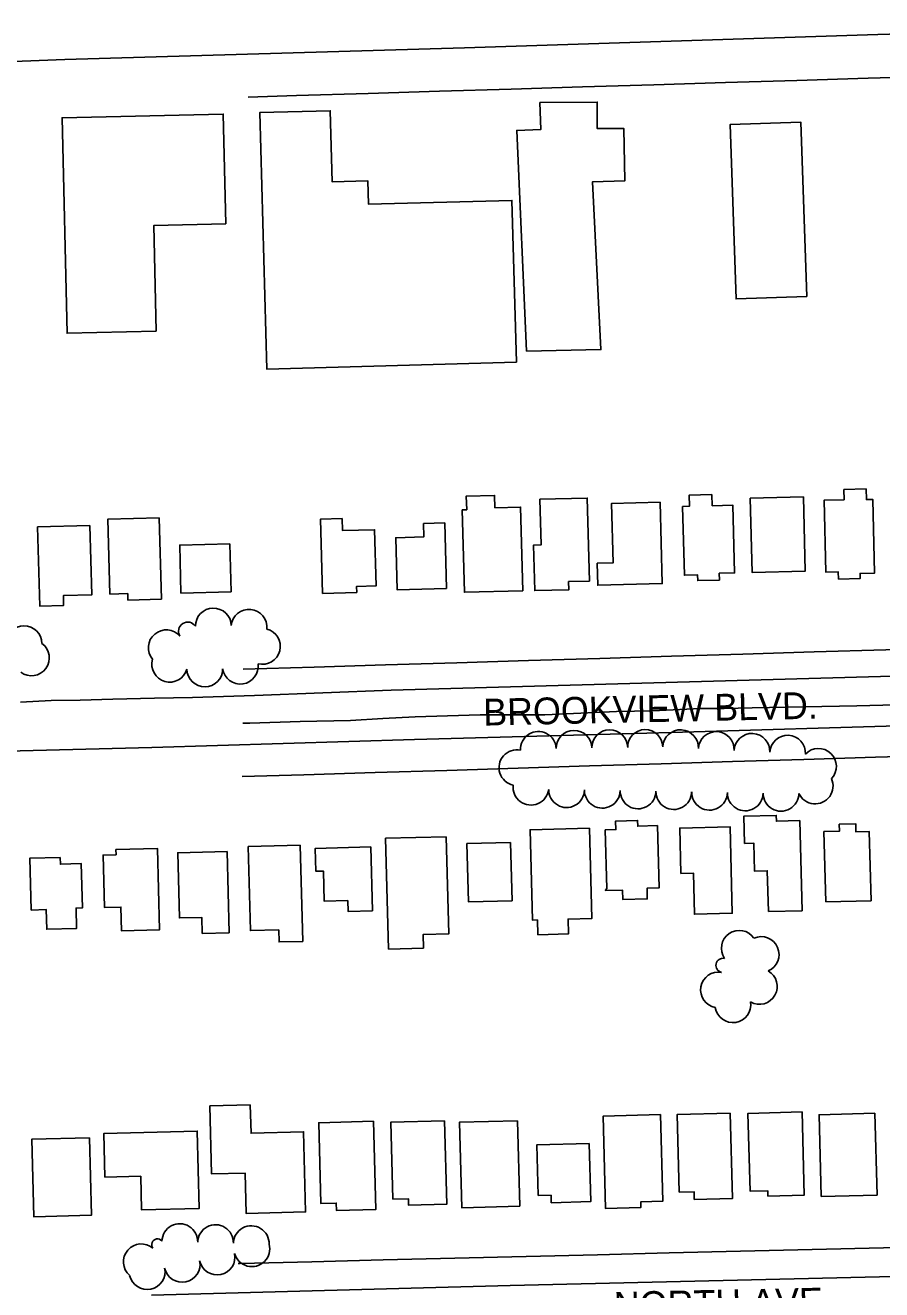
# Model space of a CAD drawing. Extents: x -25029 to 2274964, y -81170 to 687028.
# Drawn here: x -18487 to -18008, y -65240 to -64533 of the extents above; entities that cross this region are included whole.
import ezdxf

# ---------------------------------------------------------------- set-up
doc = ezdxf.new("R2010")
doc.units = 0
for name, color, linetype in [('81911BEA - RW_X_Fee_RW', 7, 'Continuous'), ('BLDG', 7, 'Continuous'), ('GE_X_CL_2000', 7, 'Continuous'), ('ROAD', 7, 'Continuous'), ('ROAD-NAME', 7, 'Continuous'), ('TREES', 7, 'Continuous')]:
    doc.layers.add(name, color=color, linetype=linetype)

msp = doc.modelspace()

# ---------------------------------------------------------------- linework, layer by layer
at = {"layer": '81911BEA - RW_X_Fee_RW'}
for points in [[(-17756.21, -64554.32), (-17775.8, -64554.92), (-17815.79, -64556.13), (-17855.77, -64557.35), (-17895.75, -64558.56), (-17935.73, -64559.78), (-17975.72, -64561), (-18015.7, -64562.21), (-18055.68, -64563.43)], [(-18055.68, -64563.43), (-18095.66, -64564.64), (-18135.65, -64565.86), (-18175.63, -64567.07), (-18215.61, -64568.29), (-18255.59, -64569.5), (-18295.58, -64570.72), (-18335.56, -64571.93), (-18362.69, -64572.76)], [(-17754.05, -64874.38), (-17846.04, -64877.18), (-17886.02, -64878.4), (-17926, -64879.61), (-17965.98, -64880.83), (-18005.96, -64882.04), (-18045.95, -64883.26)], [(-18045.95, -64883.26), (-18085.93, -64884.47), (-18125.91, -64885.69), (-18165.89, -64886.9), (-18205.88, -64888.12), (-18245.86, -64889.34), (-18285.84, -64890.55), (-18325.83, -64891.77), (-18365.44, -64892.97)], [(-17752.23, -64934.36), (-17851.79, -64937.38), (-17891.77, -64938.6), (-17931.76, -64939.82), (-17971.74, -64941.03), (-18011.72, -64942.25), (-18051.7, -64943.46)], [(-18051.7, -64943.46), (-18091.69, -64944.68), (-18131.67, -64945.89), (-18171.65, -64947.11), (-18211.63, -64948.32), (-18251.62, -64949.54), (-18291.6, -64950.75), (-18331.58, -64951.97), (-18365.96, -64953.01)], [(-17728.73, -65209.91), (-17847.23, -65212.8), (-17887.22, -65213.77), (-17927.21, -65214.75), (-17947.2, -65215.24), (-17967.2, -65215.72), (-18007.19, -65216.7), (-18047.18, -65217.67)], [(-18047.18, -65217.67), (-18087.16, -65218.65), (-18127.15, -65219.62), (-18167.14, -65220.6), (-18207.13, -65221.58), (-18247.12, -65222.55), (-18287.11, -65223.53), (-18327.1, -65224.5), (-18367.09, -65225.48), (-18368.31, -65225.5)]]:
    msp.add_lwpolyline(points, dxfattribs=at)
at = {"layer": 'BLDG'}
for points in [[(-18212.62, -64721.2), (-18215.12, -64630.57), (-18295.29, -64632.78), (-18295.65, -64619.71), (-18315.62, -64620.26), (-18316.72, -64580.41), (-18356.17, -64581.5), (-18352.21, -64725.05)], [(-18207.02, -64715.01), (-18212.41, -64591.45), (-18198.99, -64590.97), (-18199.41, -64575.88), (-18167.33, -64575.54), (-18167.47, -64590.28), (-18152.56, -64590.35), (-18152.01, -64619.65), (-18170.01, -64620.2), (-18165.28, -64714.06)], [(-18414.09, -64703.77), (-18415.47, -64644.64), (-18375.23, -64643.7), (-18376.66, -64582.3), (-18466.78, -64584.39), (-18463.98, -64704.93)], [(-18050.1, -64684.33), (-18053.48, -64586.79), (-18093.05, -64588.16), (-18089.67, -64685.7)], [(-18029.21, -64798.08), (-18029.36, -64792.39), (-18016.92, -64792.07), (-18016.77, -64798.03), (-18013.24, -64797.93), (-18012.17, -64839.11), (-18020.33, -64839.33), (-18020.26, -64842.2), (-18032.36, -64842.52), (-18032.47, -64838.49), (-18039.38, -64838.67), (-18040.43, -64798.37)], [(-18209, -64849.04), (-18210.22, -64802.24), (-18224.66, -64802.62), (-18224.84, -64795.66), (-18240.62, -64796.07), (-18240.42, -64803.73), (-18242.87, -64803.8), (-18241.67, -64849.9)], [(-18199.43, -64797.86), (-18198.76, -64823.37), (-18202.97, -64823.48), (-18202.3, -64848.96), (-18183.26, -64848.46), (-18183.38, -64843.93), (-18171.72, -64843.62), (-18172.93, -64797.17)], [(-18132.23, -64799.46), (-18131.04, -64845), (-18167.08, -64845.94), (-18167.4, -64833.69), (-18158.5, -64833.45), (-18159.37, -64800.17)], [(-18103.13, -64801.49), (-18103.29, -64795.26), (-18115.96, -64795.59), (-18115.8, -64801.8), (-18119.6, -64801.9), (-18118.6, -64840.34), (-18111.23, -64840.14), (-18111.14, -64843.38), (-18099, -64843.07), (-18099.1, -64839.28), (-18090.5, -64839.06), (-18091.49, -64801.19)], [(-18081.84, -64797.29), (-18080.76, -64838.8), (-18050.95, -64838.02), (-18052.04, -64796.51)], [(-18451.2, -64812.54), (-18450.19, -64851.34), (-18466.08, -64851.76), (-18465.94, -64857.25), (-18479.35, -64857.6), (-18480.51, -64813.31)], [(-18412.42, -64808.17), (-18411.23, -64853.73), (-18429.96, -64854.22), (-18430.05, -64850.63), (-18440.03, -64850.89), (-18441.13, -64808.92)], [(-18310.03, -64808.63), (-18309.85, -64815.37), (-18291.97, -64814.9), (-18291.15, -64846.35), (-18301.99, -64846.63), (-18301.9, -64849.99), (-18321.08, -64850.49), (-18322.17, -64808.95)], [(-18264.66, -64811.44), (-18264.47, -64818.94), (-18280.08, -64819.35), (-18279.32, -64848.47), (-18251.73, -64847.74), (-18252.69, -64811.12)], [(-18372.97, -64822.74), (-18372.26, -64849.61), (-18400.29, -64850.35), (-18401, -64823.48)], [(-18071.61, -65028.59), (-18072.21, -65005.74), (-18079.43, -65005.93), (-18079.84, -64990.26), (-18084.97, -64990.4), (-18085.37, -64975.23), (-18067.22, -64974.76), (-18067.13, -64978.01), (-18054.09, -64977.67), (-18052.77, -65028.09)], [(-18171.68, -64981.95), (-18170.36, -65032.42), (-18183.71, -65032.77), (-18183.49, -65041.12), (-18200.58, -65041.56), (-18200.8, -65033.26), (-18203.61, -65033.33), (-18204.94, -64982.82)], [(-18162.96, -65016.85), (-18153.16, -65016.6), (-18153.02, -65021.87), (-18139.35, -65021.51), (-18139.51, -65015.48), (-18132.76, -65015.3), (-18133.67, -64980.5), (-18144.69, -64980.79), (-18144.77, -64977.6), (-18157.07, -64977.93), (-18156.95, -64982.74), (-18162.89, -64982.9), (-18162.03, -65015.71)], [(-18120.54, -65007.25), (-18113.59, -65007.07), (-18112.98, -65030.04), (-18091.79, -65029.49), (-18093.06, -64981.1), (-18121.21, -64981.83)], [(-18039.53, -65023.22), (-18040.56, -64983.85), (-18031.88, -64983.62), (-18031.98, -64979.71), (-18022.76, -64979.47), (-18022.64, -64984.04), (-18015.15, -64983.84), (-18014.14, -65022.56)], [(-18345.55, -65038.77), (-18345.37, -65045.59), (-18332.19, -65045.24), (-18333.6, -64991.43), (-18362.64, -64992.19), (-18361.41, -65039.18)], [(-18251.9, -64986.71), (-18250.48, -65041.05), (-18264.83, -65041.43), (-18264.63, -65049.04), (-18284.14, -65049.55), (-18285.76, -64987.59)], [(-18215.91, -64989.93), (-18215.05, -65022.54), (-18239.39, -65023.18), (-18240.25, -64990.57)], [(-18467.88, -64998.23), (-18467.78, -65002.05), (-18456.08, -65001.74), (-18455.43, -65026.52), (-18458.96, -65026.62), (-18458.66, -65038.04), (-18475.35, -65038.48), (-18475.64, -65027.51), (-18484.05, -65027.74), (-18484.81, -64998.67)], [(-18436.7, -64993.88), (-18436.63, -64996.79), (-18443.9, -64996.98), (-18443.13, -65026.29), (-18433.86, -65026.05), (-18433.51, -65039.39), (-18412.31, -65038.83), (-18413.5, -64993.27)], [(-18374.52, -64994.98), (-18373.33, -65040.44), (-18388.42, -65040.83), (-18388.65, -65031.82), (-18401.13, -65032.14), (-18402.08, -64995.7)], [(-18293.19, -65028.12), (-18306.79, -65028.47), (-18306.95, -65022.42), (-18320.12, -65022.76), (-18320.56, -65005.94), (-18324.79, -65006.05), (-18325.12, -64993.22), (-18294.12, -64992.41)], [(-18361.49, -65136.75), (-18361.07, -65152.59), (-18331.71, -65151.82), (-18330.54, -65196.64), (-18363.87, -65197.52), (-18364.46, -65174.9), (-18383.12, -65175.39), (-18384.11, -65137.34)], [(-18292.49, -65145.91), (-18291.2, -65195.23), (-18313.3, -65195.81), (-18313.41, -65191.74), (-18321.98, -65191.97), (-18323.17, -65146.71)], [(-18252.81, -65145.62), (-18251.59, -65192.4), (-18272.91, -65192.96), (-18273.01, -65189.25), (-18281.67, -65189.48), (-18282.8, -65146.4)], [(-18211.95, -65145.66), (-18210.7, -65193.43), (-18243.2, -65194.28), (-18244.45, -65146.51)], [(-18131.98, -65142.19), (-18130.71, -65190.72), (-18143.06, -65191.04), (-18142.98, -65194.26), (-18162.68, -65194.77), (-18164.03, -65143.03)], [(-18092.91, -65141.31), (-18091.66, -65189.07), (-18113.05, -65189.63), (-18113.16, -65185.34), (-18121.45, -65185.56), (-18122.59, -65142.09)], [(-18052.74, -65140.72), (-18051.52, -65187.23), (-18071.85, -65187.77), (-18071.92, -65184.77), (-18081.88, -65185.03), (-18083.02, -65141.52)], [(-18012, -65141.45), (-18010.81, -65187.19), (-18042.02, -65188.01), (-18043.22, -65142.27)], [(-18442.82, -65177.18), (-18422.81, -65176.65), (-18422.31, -65195.54), (-18390.05, -65194.7), (-18391.18, -65151.46), (-18443.45, -65152.83)], [(-18451.55, -65155.12), (-18450.41, -65198.5), (-18482.68, -65199.35), (-18483.82, -65155.96)], [(-18200.46, -65187.53), (-18193.21, -65187.34), (-18193.1, -65191.49), (-18171.04, -65190.91), (-18171.89, -65158.39), (-18201.2, -65159.16)]]:
    msp.add_lwpolyline(points, close=True, dxfattribs=at)
at = {"layer": 'GE_X_CL_2000'}
msp.add_lwpolyline([(-17702.27, -64903.92), (-17730.66, -64904.33), (-17776.21, -64905.61), (-17839.63, -64908.32), (-17899.94, -64910.18), (-17956.79, -64911.69), (-18022.18, -64913.43), (-18080.69, -64914.47), (-18096.29, -64915), (-18109.58, -64914.95), (-18136.53, -64916.16), (-18156.57, -64916.7), (-18176.62, -64917.47), (-18196.65, -64918.47), (-18215.36, -64918.41), (-18232.94, -64918.57), (-18251.08, -64918.98), (-18269.22, -64919.63), (-18287.35, -64920.51), (-18305.46, -64921.63), (-18333.66, -64922.23), (-18361.84, -64923.07), (-18365.7, -64923.22)], dxfattribs=at)
at = {"layer": 'ROAD'}
for points in [[(-17826.46, -64532.6), (-18010.33, -64537.81), (-18241.7, -64545.16), (-18465.23, -64551.73), (-18660.98, -64559.38), (-18871.14, -64566.48), (-18877.69, -64567.27), (-18892.09, -64571.11), (-18899.34, -64575.82), (-18901.73, -64578.58), (-18905.7, -64583.13), (-18911.8, -64593.68), (-18913.12, -64597.13), (-18916.08, -64611.9), (-18915.6, -64619.47), (-18914.3, -64627.24), (-18892.57, -64748.36)], [(-17713.31, -64748.36), (-17711.67, -64869.08), (-17712.88, -64875.22), (-17714.91, -64879.71), (-17717.8, -64883.49), (-17722.09, -64885.99), (-17726.03, -64887.41), (-17729.83, -64888.11), (-18008.79, -64897.11), (-18282.72, -64904.59), (-18359.18, -64907.58), (-18393.92, -64908.84), (-18415.15, -64909.21), (-18438.39, -64909.67), (-18456.73, -64910.21), (-18472.92, -64910.5), (-18490.03, -64911.31)], [(-18512.61, -64939.18), (-18416.5, -64936.79), (-18269.61, -64932.26), (-18125.95, -64928.28), (-17986.61, -64924.22)], [(-17977.73, -65232.18), (-18216, -65237.88), (-18416.7, -65243.29)]]:
    msp.add_lwpolyline(points, dxfattribs=at)
at = {"layer": 'TREES'}
for centre, radius, start, end in [((-18382.17, -64868.74), 10, 1.22271, 181.22271), ((-18362.22, -64869.5), 10, 354.44758, 174.44758), ((-18488.06, -64878.62), 10, 0.45908, 180.45908), ((-18408.52, -64880.95), 10, 40.09531, 220.09531), ((-18396.52, -64871.73), 5.16, 32.54801, 212.54801), ((-18354.72, -64880.16), 10, 255.80468, 75.80468), ((-18483.97, -64886.61), 10, 233.781, 53.781), ((-18406.57, -64890.19), 10, 163.73184, 343.73184), ((-18367.07, -64891.26), 10, 188.09674, 8.09674), ((-18386.97, -64892.83), 10, 180.92409, 0.92409), ((-18200.33, -64937.8), 10, 2.47173, 182.47173), ((-18180.34, -64937.2), 10, 0.99047, 180.99047), ((-18160.34, -64936.85), 10, 0.99047, 180.99047), ((-18140.54, -64936.51), 9.8, 0.99047, 180.99047), ((-18120.75, -64936.85), 10, 357.07174, 177.07174), ((-18100.78, -64937.87), 10, 357.07174, 177.07174), ((-18080.8, -64938.9), 10, 357.07174, 177.07174), ((-18060.83, -64939.92), 10, 357.07174, 177.07174), ((-18212.35, -64948.03), 10, 78.28604, 258.28604), ((-18043.58, -64947.3), 10, 316.56949, 136.56949), ((-18045.43, -64958.3), 10, 204.34506, 24.34506), ((-18204.45, -64959), 10, 173.23654, 353.23654), ((-18184.52, -64960.36), 10, 178.94895, 358.94895), ((-18164.53, -64960.72), 10, 178.94895, 358.94895), ((-18144.53, -64961.09), 10, 178.94895, 358.94895), ((-18124.53, -64961.46), 10, 178.94895, 358.94895), ((-18104.54, -64961.82), 10, 178.94895, 358.94895), ((-18084.54, -64962.19), 10, 178.94895, 358.94895), ((-18064.54, -64962.4), 10, 179.86272, 359.86272), ((-18087.91, -65049.1), 10, 34.42865, 214.42865), ((-18075.67, -65052.62), 10, 293.5336, 113.5336), ((-18096.96, -65058.67), 3.99, 78.52309, 258.52309), ((-18076.62, -65070.48), 10, 240.41981, 60.41981), ((-18099.53, -65072.43), 10, 79.74442, 259.74442), ((-18091.43, -65080.72), 10, 188.88323, 8.88323), ((-18400.94, -65213.27), 10, 358.36811, 178.36811), ((-18380.94, -65213.84), 10, 358.36811, 178.36811), ((-18360.95, -65214.41), 10, 358.36811, 178.36811), ((-18422.48, -65224.56), 10, 49.2952, 229.2952), ((-18413.45, -65214.98), 3.21, 38.4635, 218.4635), ((-18360.61, -65217.29), 10, 195.04315, 15.04315), ((-18399.64, -65226.02), 10, 191.7885, 11.7885), ((-18380.06, -65221.93), 10, 191.7885, 11.7885), ((-18419.22, -65230.1), 10, 191.7885, 11.7885)]:
    msp.add_arc(centre, radius, start, end, dxfattribs=at)

# ---------------------------------------------------------------- texts
at = {"layer": 'ROAD-NAME'}
for s, p in [('BROOKVIEW BLVD.', (-18231.04, -64924.53)), ('NORTH AVE.', (-18157.94, -65256.46))]:
    msp.add_text(s, height=15, rotation=1.19807, dxfattribs=at).set_placement(p)

doc.saveas('drawing.dxf')
